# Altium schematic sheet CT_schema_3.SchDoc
size 395 x 205 mm
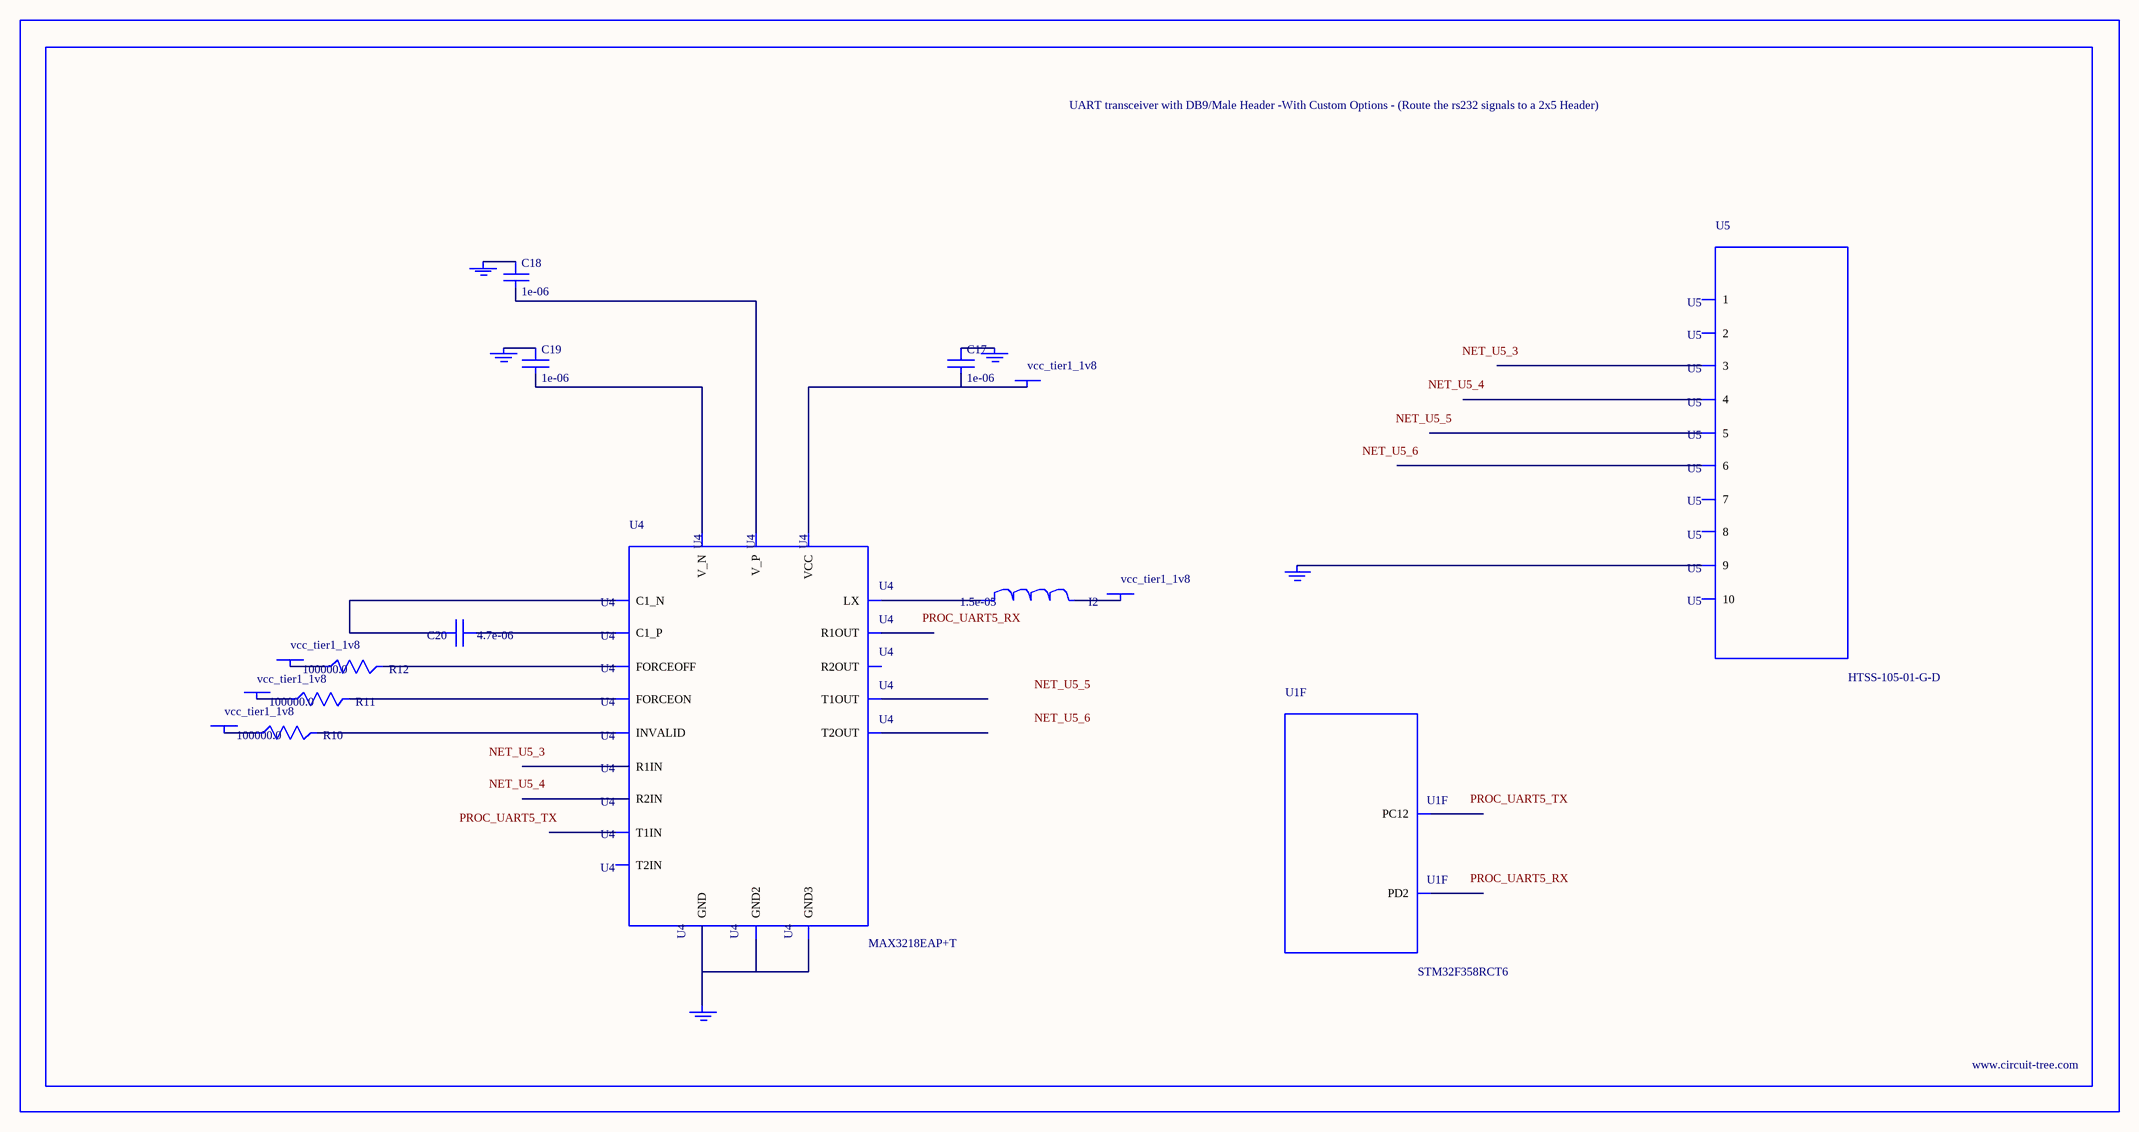
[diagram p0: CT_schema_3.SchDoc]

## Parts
BORDER2  (no value)
C17  1e-06  [C0603]
C18  1e-06  [C0603]
C19  1e-06  [C0603]
C20  4.7e-06  [C0805]
GND_INSTANCE_2_0  (no value)
GND_INSTANCE_2_1  (no value)
GND_INSTANCE_2_2  (no value)
GND_INSTANCE_2_3  (no value)
GND_INSTANCE_2_4  (no value)
I2  1.5e-05  [L1210]
POWER_INSTANCE_2_0  vcc_tier1_1v8
POWER_INSTANCE_2_1  vcc_tier1_1v8
POWER_INSTANCE_2_2  vcc_tier1_1v8
POWER_INSTANCE_2_3  vcc_tier1_1v8
POWER_INSTANCE_2_4  vcc_tier1_1v8
R10  100000.0  [R0603]
R11  100000.0  [R0603]
R12  100000.0  [R0603]
U1  STM32F358RCT6  [LQFP64]  (part F of 7)
U4  MAX3218EAP+T  [SSOP-20]
U5  HTSS-105-01-G-D  [HTSS-105-01-G-D]

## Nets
NetC17_1: C17.1 GND_INSTANCE_2_0.0(GND)
NetC17_2: C17.2 POWER_INSTANCE_2_4.0(PWR) U4.6(VCC)
NetC18_1: C18.1 GND_INSTANCE_2_2.0(GND)
NetC18_2: C18.2 U4.19(V_P)
NetC19_1: C19.1 GND_INSTANCE_2_1.0(GND)
NetC19_2: C19.2 U4.15(V_N)
NetC20_1: C20.1 U4.18(C1_P)
NetC20_2: C20.2 U4.16(C1_N)
NetGND_INSTANCE_2_3_0: GND_INSTANCE_2_3.0(GND) U4.5(GND) U4.17(GND2) U4.20(GND3)
NetGND_INSTANCE_2_4_0: GND_INSTANCE_2_4.0(GND) U5.9
NetI2_1: I2.1 U4.1(LX)
NetI2_2: I2.2 POWER_INSTANCE_2_0.0(PWR)
NetPOWER_INSTANCE_2_1_0: POWER_INSTANCE_2_1.0(PWR) R10.1
NetPOWER_INSTANCE_2_2_0: POWER_INSTANCE_2_2.0(PWR) R11.1
NetPOWER_INSTANCE_2_3_0: POWER_INSTANCE_2_3.0(PWR) R12.1
NetR10_2: R10.2 U4.2(INVALID)
NetR11_2: R11.2 U4.3(FORCEON)
NetR12_2: R12.2 U4.4(FORCEOFF)

Not connected (* = marked no-connect by the designer): U1 53(PC12) 54(PD2); U4 7(T1IN) 8(T2IN) 9(R1OUT) 10(R2OUT) 11(R2IN) 12(R1IN) 13(T2OUT) 14(T1OUT); U5 1 2 3 4 5 6 7 8 10

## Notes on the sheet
- Labels drawn without touching a wire or pin: NET_U5_3, NET_U5_4, NET_U5_5, NET_U5_6, PROC_UART5_RX, PROC_UART5_TX

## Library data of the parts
BORDER2 = BORDER_PAGE2
C17-C19 = C0603C105K3RACTU
C20 = C0805C475K4RACTU
GND_INSTANCE_2_0-GND_INSTANCE_2_4 = GND
I2 = L1210R150MDWIT
POWER_INSTANCE_2_0-POWER_INSTANCE_2_4 = PWR
R10-R12 = RC0603JR-07100KL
